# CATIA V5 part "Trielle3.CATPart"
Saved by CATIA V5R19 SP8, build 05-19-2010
Part number: Trielle
Bounding box of the stored display mesh (mm): x -320 to 20, y 0 to 50, z -30 to 30
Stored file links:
  C:\Users\ThinkMotion\Desktop\EU_thinkMotion\iao\IAO_MMS_Groupe3\yschmidt\Train1434_yschmidt\Train1434_yschmidt\Trielle3.CATPart
  C:\Users\ThinkMotion\Desktop\EU_thinkMotion\iao\IAO_MMS_Groupe3\yschmidt\Train1434_yschmidt\Train1434_yschmidt\AssemblageTrainOptimise.CATProduct
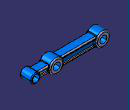
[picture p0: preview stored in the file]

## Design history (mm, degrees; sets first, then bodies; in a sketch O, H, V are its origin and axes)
Set1
  Line1 to Line3: linked copy from another document
Set2
  Plane1: type Offset, RefPlane yz-plane, Offset 70, reversed
Body1 (main body)
  Sketch1 on zx-plane, origin (0, 0, 0), H (-1, 0, 0), V (0, 0, 1)
    circle A1 centre (0, 0) radius 20
    circle A2 centre (90, 0) radius 30
    circle A3 centre (290, 0) radius 30
    reference projected point E1 (290, 0) from Line3
    reference projected point E2 (0, 0) from Line2
    reference projected point E3 (90, 0) from Line1
    radius A3 = 30
    radius A2 = 30
    radius A1 = 20
    concentricity: E1 A3, E2 A1, E3 A2
  Pad1: profile Sketch1, direction (0, 1, 0), length 50
  Sketch2 on yz-plane, origin (0, 0, 0), H (0, 1, 0), V (0, 0, 1)
    line L1 (10, 7) -> (5, 7)
    line L2 (40, 7) -> (40, -7)
    line L3 (40, -7) -> (45, -7)
    line L4 (10, -7) -> (10, 7)
    point P5 (5, 7)
    line L5 (45, 7) -> (45, 15)
    line L6 (45, 15) -> (5, 15)
    line L7 (5, 15) -> (5, 7)
    point P6 (45, 7)
    point P7 (45, 15)
    point P8 (5, 15)
    axis line L8 (-6.6001, 0) -> (69.3419, 0)
    point P11 (45, -15)
    point P12 (45, -7)
    line L9 (45, -7) -> (45, -15)
    point P13 (5, -15)
    point P14 (5, -7)
    line L10 (5, -15) -> (5, -7)
    line L11 (45, 7) -> (40, 7)
    line L12 (5, -7) -> (10, -7)
    point P15 (5, -15)
    point P16 (45, -15)
    line L13 (45, -15) -> (5, -15)
    reference projected line E1 (50, 20) -> (50, -20) from edge [face of Pad1 from Sketch1.A1 | end face of Pad1]
    reference projected line E2 (0, 20) -> (0, -20) from edge [start face of Pad1 | face of Pad1 from Sketch1.A1]
    distance L5 E1 = 5
    distance L7 E2 = 5
    distance L8 L11 = 7
    distance L2 L4 = 30
    distance L2 L5 = 5
    distance L6 L8 = 15
    horizontal: L1 H, L3 H, L6 H, L8 H, L11 H, L12 H
    vertical: L2 V, L4 V, L5 V, L7 V
    symmetry: P7 P11 L8, P6 P12 L8, L5 L9 L8, P8 P13 L8, P5 P14 L8, L7 L10 L8, P8 P15 L8, P7 P16 L8, L6 L13 L8
    coincidence: L1 L11, L3 L12, H L8
  Pad2: profile Sketch2, direction (-1, 0, 0), length 70
  Sketch3 on end face of Pad1, origin (6.1028, 50, 9.6712), H (1, 0, 0), V (0, 0, -1)
    point P1 (-6.1028, 9.6712)
    reference projected point E1 (-6.1028, 9.6712) from Line2
    coincidence: P1 E1
  Hole1: placed by Sketch3, at (0, 50, 0) direction (0, -1, 0), diameter 30, through (limit type 6)
  Fillet1: radius 10, on edge [face of Pad1 from Sketch1.A2 | face of Pad2] (x2); edge [face of Pad2 | face of Pad1 from Sketch1.A2] (x2); edge [face of Pad2 | face of Pad1 from Sketch1.A3]; edge [face of Pad1 from Sketch1.A3 | face of Pad2], deactivated
  Fillet2: radius 3, on edge [start face of Pad1 | face of Pad1 from Sketch1.A1]; edge [face of Pad1 from Sketch1.A1 | end face of Pad1]
  Sketch4 on Plane1, origin (-70, 0, 0), H (0, 1, 0), V (0, 0, 1)
    line L1 (5, 20) -> (45, 20)
    line L2 (45, 20) -> (45, 10)
    line L3 (45, -20) -> (5, -20)
    line L4 (5, -20) -> (5, -10)
    point P5 (5, 10)
    line L5 (5, 10) -> (10, 10)
    line L6 (10, 10) -> (10, -10)
    line L7 (10, -10) -> (5, -10)
    point P9 (45, 10)
    line L8 (45, 10) -> (40, 10)
    line L9 (40, 10) -> (40, -10)
    line L10 (40, -10) -> (45, -10)
    point P11 (40, -10)
    line L11 (45, -10) -> (45, -20)
    line L12 (5, 10) -> (5, 20)
    reference intersected line E1 (50, 30) -> (50, -30) from end face of Pad1
    reference intersected line E2 (0, -30) -> (0, 30) from start face of Pad1
    length L9 = 20
    length L2 = 10
    length L11 = 10
    distance L9 L11 = 5
    length L7 = 5
    distance H L7 = 10
    distance L2 E1 = 5
    distance L4 E2 = 5
    horizontal: L1 H, L3 H, L5 H, L7 H, L8 H, L10 H
    vertical: L2 V, L4 V, L6 V, L9 V, L11 V, L12 V
    coincidence: P5 L4, P9 L5, P11 L7, L2 L11, L4 L12
  Pad3: profile Sketch4, direction (-1, 0, 0), length 200
  Sketch5 on end face of Pad1, origin (-82.2766, 50, 0), H (1, 0, 0), V (0, 0, -1)
    point P1 (-7.7234, 0)
    reference projected point E1 (-7.7234, 0) from Line1
    coincidence: P1 E1
  Hole2: placed by Sketch5, at (-90, 50, 0) direction (0, -1, 0), diameter 30, through (limit type 6)
  Sketch6 on end face of Pad1, origin (-273.6474, 50, 9.5601), H (1, 0, 0), V (0, 0, -1)
    point P1 (-16.3526, 9.5601)
    reference projected point E1 (-16.3526, 9.5601) from Line3
    coincidence: P1 E1
  Hole3: placed by Sketch6, at (-290, 50, 0) direction (0, -1, 0), diameter 30, through (limit type 6)
  Fillet3: radius 5, on edge [face of Pad1 from Sketch1.A2 | end face of Pad1]; edge [start face of Pad1 | face of Pad1 from Sketch1.A2]; edge [start face of Pad1 | face of Pad1 from Sketch1.A3]; edge [face of Pad1 from Sketch1.A3 | end face of Pad1]
  Fillet4: radius 5, on edge [face of Pad3 from Sketch4.L1 | face of Pad3 from Sketch4.L12]; edge [face of Pad3 from Sketch4.L2 | face of Pad3 from Sketch4.L1]; edge [face of Pad3 from Sketch4.L3 | face of Pad3 from Sketch4.L11]; edge [face of Pad3 from Sketch4.L4 | face of Pad3 from Sketch4.L3]; edge [face of Pad2 from Sketch2.L10 | face of Pad2 from Sketch2.L13]; edge [face of Pad2 from Sketch2.L13 | face of Pad2 from Sketch2.L9]; edge [face of Pad2 from Sketch2.L5 | face of Pad2 from Sketch2.L6]; edge [face of Pad2 from Sketch2.L6 | face of Pad2 from Sketch2.L7]
  Fillet5: radius 3, on edge [face of Pad3 from Sketch4.L7 | face of Pad3 from Sketch4.L4]; edge [face of Pad3 from Sketch4.L12 | face of Pad3 from Sketch4.L5]; edge [face of Pad3 from Sketch4.L5 | face of Pad3 from Sketch4.L6]; edge [face of Pad3 from Sketch4.L6 | face of Pad3 from Sketch4.L7]; edge [face of Pad3 from Sketch4.L8 | face of Pad3 from Sketch4.L2]; edge [face of Pad3 from Sketch4.L9 | face of Pad3 from Sketch4.L8]; edge [face of Pad3 from Sketch4.L10 | face of Pad3 from Sketch4.L9]; edge [face of Pad3 from Sketch4.L11 | face of Pad3 from Sketch4.L10]
  Fillet6: radius 3, on edge [face of Pad2 from Sketch2.L11 | face of Pad2 from Sketch2.L5]; edge [face of Pad2 from Sketch2.L9 | face of Pad2 from Sketch2.L3]; edge [face of Pad2 from Sketch2.L12 | face of Pad2 from Sketch2.L10]; edge [face of Pad2 from Sketch2.L7 | face of Pad2 from Sketch2.L1]; edge [face of Pad2 from Sketch2.L1 | face of Pad2 from Sketch2.L4]; edge [face of Pad2 from Sketch2.L3 | face of Pad2 from Sketch2.L2]; edge [face of Pad2 from Sketch2.L2 | face of Pad2 from Sketch2.L11]; edge [face of Pad2 from Sketch2.L4 | face of Pad2 from Sketch2.L12]
  Fillet7: radius 3, on edge [face of Pad1 from Sketch1.A1 | face of Pad2 from Sketch2.L4]; edge [face of Pad1 | face of Pad2 from Sketch2.L4]
  Fillet8: radius 5, on edge [face of Pad1 from Sketch1.A2 | face of Pad3 from Sketch4.L6]; edge [face of Pad1 | face of Pad3 from Sketch4.L6]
